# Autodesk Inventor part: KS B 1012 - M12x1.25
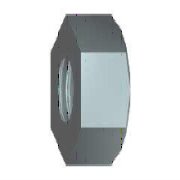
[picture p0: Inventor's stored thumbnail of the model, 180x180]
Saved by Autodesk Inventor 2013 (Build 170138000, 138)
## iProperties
IsCustomPart: 0
Created: 2009-02
Part Number: KS B 1012 - M12x1.25
Material: 강, 연강
Description: 6각 너트
Document SubType Name: Modeling
Standard: KS B 1012
Designer: KYOUNG IL JANG
Standards Organization: KS
Language: ko-KR
Size Designation: M12x1.25
Categories: <MemberInstance><Categories><Category DisplayName="조임쇠" InternalName="e4da775c-781d-43d5-af7c-5136215cf5a6" Mnemonic="FSTN"><Category DisplayName="너트" InternalN
Density: 1 g/cm^3
Author: KYOUNG IL JANG
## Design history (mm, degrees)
sketch "스케치1"
  geometry: L1 (10.97, 0)-(5.485, -9.5); L2 (5.485, -9.5)-(-5.485, -9.5); L3 (-5.485, -9.5)-(-10.97, 0); L4 (-10.97, 0)-(-5.485, 9.5); L5 (-5.485, 9.5)-(5.485, 9.5); L6 (5.485, 9.5)-(10.97, 0); 2 further points
  constraints: 12 end point, 1 coincident, 1 horizontal, 11 other
  dimensions: "d0" = 21.93931 distance of L1.start L3.end (= 1.1547 x SW)
extrude "본체" new body sketch "스케치1" distance "d1" = 10 (= KOH); taper "d2" = 0 deg
sketch "스케치2"
  geometry: 1 further point
hole "스레드" sketch "스케치2" diameter "d6" = 10.647; stored, may be unused: countersink angle "d10" = 82 deg, drill point angle "d12" = 118 deg; dims "d7" = 12.7, "d8" = 9.525, "d9" = 6.35, "d11" = 19.05
sketch "스케치3"
  geometry: L1 (0, 10.97)-(10, 10.97) reference; L2 (10, 5.485)-(10, 10.97) reference; L3 (-2, 0)-(12, 0) reference; L4 (9.151, 10.97)-(10, 9.5)
  constraints: 2 end point, 2 point on line
  dimensions: "d3" = 19 diameter of L4.end L3 (= SW01); "d4" = 30 deg angle of L2 L4 (= ANG2)
revolve "모따기3" sketch "스케치3" stored, may be unused: angle "d5" = 90 deg
workaxis "Work Axis1"
workplane "Work Plane1"
body "Solid1"
chamfer "모따기1" distance "d13" = 0.67658 (= -0.5 x GD1 + 0.5 x NND); stored, may be unused: angle "d14" = 30 deg, second distance "d21" = 0.67658 (= -0.5 x GD1 + 0.5 x NND)
chamfer "모따기2" distance "d15" = 0.67658 (= -0.5 x GD1 + 0.5 x NND); stored, may be unused: angle "d16" = 30 deg, second distance "d22" = 0.67658 (= -0.5 x GD1 + 0.5 x NND)
other parameters: "ANG2" = 30 deg [user parameter; used in 1 equation term], "NND" = 12 [user parameter; used in 4 equation terms], "KOH" = 10 [user parameter; used in 1 equation term], "SW" = 19 [user parameter; used in 3 equation terms], "SW01" = 19 (= SW) [user parameter; used in 1 equation term], "GD1" = 10.64684 (computed from THREADDIA, PTC, TOA) [user parameter; used in 4 equation terms], "d19" = 0, "d20" = 0, "d24" = 0, "d25" = 0, "GUL" = 0.67658 (= 0.541266 x PTC) [user parameter], "TPU" = 8 (computed from PTC) [user parameter], "TOA" = 30 deg [user parameter; used in 1 equation term], "PTC" = 1.25 [user parameter; used in 4 equation terms], "E0" = 21.945 (= 1.155 x SW) [user parameter], "THREADDIA" = 12 [user parameter; used in 1 equation term], "GAL" = 0.67658 (= 0.541266 x PTC) [user parameter]
